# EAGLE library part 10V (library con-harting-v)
CONNECTOR
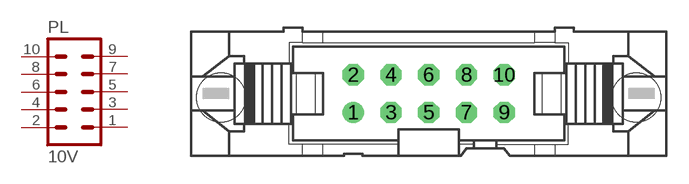
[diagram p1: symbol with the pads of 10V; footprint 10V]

Designator prefix PL

## 10V (OC_FARNELL: unknown; OC_NEWARK: unknown)  [10V]
1  1  pas
2  2  pas
3  3  pas
4  4  pas
5  5  pas
6  6  pas
7  7  pas
8  8  pas
9  9  pas
10  10  pas

## Footprint 10V (pad centres in mm)
CONNECTOR
drill 0.914 round: 1 -5.08,-1.27
drill 0.914 octagon: 2 -5.08,1.27; 3 -2.54,-1.27; 4 -2.54,1.27; 5 0,-1.27; 6 0,1.27; 7 2.54,-1.27; 8 2.54,1.27; 9 5.08,-1.27; 10 5.08,1.27
hole 3.302 at 13.97,-0.254
hole 3.302 at -13.97,-0.254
